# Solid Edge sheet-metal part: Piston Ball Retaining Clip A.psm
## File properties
Title: Piston Ball Retaining Clip
Author: Dan
Comments: Spring Steel Strip Width 38.mm x 1.mm Thick  Strip Steel (Orders) 011 763 4261Joleen  Brakpan 011 744 4010  Min order 250.kg  Starco 011-493-6558  ???
Template: Normal.psm
Last saved by: Dan
Revision: 35
Application: Solid Edge
Density: 0 kg/mm^3
Accuracy: 0.99
Material Thickness: 0.8 mm
Bend Radius: 3 mm
Relief Width: 3 mm
Relief Length: 3 mm
Neutral Factor: 0.33
Minimum Arc Length: 0.1 mm
Deviational Tolerance: 0.1 mm
Document Number: P52-014
Project Name: Piston Pump P52
Material: steel
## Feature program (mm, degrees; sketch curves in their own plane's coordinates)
base tab "unnamed BaseTab 1"
dimple "unnamed Dimple 1"
drawn cutout "DrawnCutout_4"
sheet metal cutout "unnamed SheetMetalCutout 1"
pattern "unnamed Pattern 1" of "unnamed SheetMetalCutout 1"
sheet metal cutout "unnamed SheetMetalCutout 2"
sheet metal cutout "unnamed SheetMetalCutout 3"
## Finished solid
Body 1: solid body, 86 faces, 180 edges, 96 vertices.
  Faces by surface: plane 29, spline 24, torus 18, cylinder 9, cone 6
  Edges by curve: line 84, circle 48, intersection 36, curve on surface 12
Bounding box of the edges (mm; curved faces can reach further): 14.067 x 15.680 x 11.700, from (-6.0672, -7.8615, -9.6) to (8, 7.8181, 2.1).
Cylindrical faces by radius (mm): R2.5 x3, R7.2 x3, R8 x3
Conical faces (half-angle, radius in mm at the cone's reference point): 15 deg R4.2273 x3, 15 deg R5 x3
Toroidal faces (ring radius, tube radius in mm): R4.2327 r0.2 x3, R4.2327 r1 x3, R6.0231 r0.6 x3, R6.0231 r1.4 x3, R6.8 r0.4 x3, R6.8 r1.2 x3
Planar faces by outward normal: +z 4, -y 2, -z 7, oblique 16
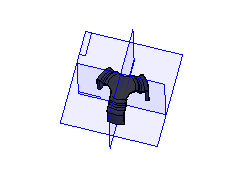
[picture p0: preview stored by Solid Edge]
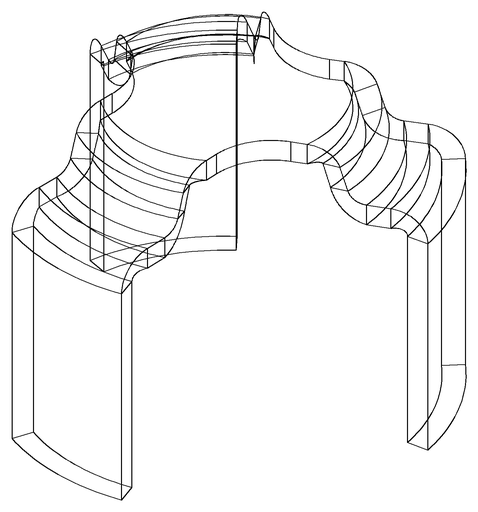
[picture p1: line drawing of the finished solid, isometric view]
